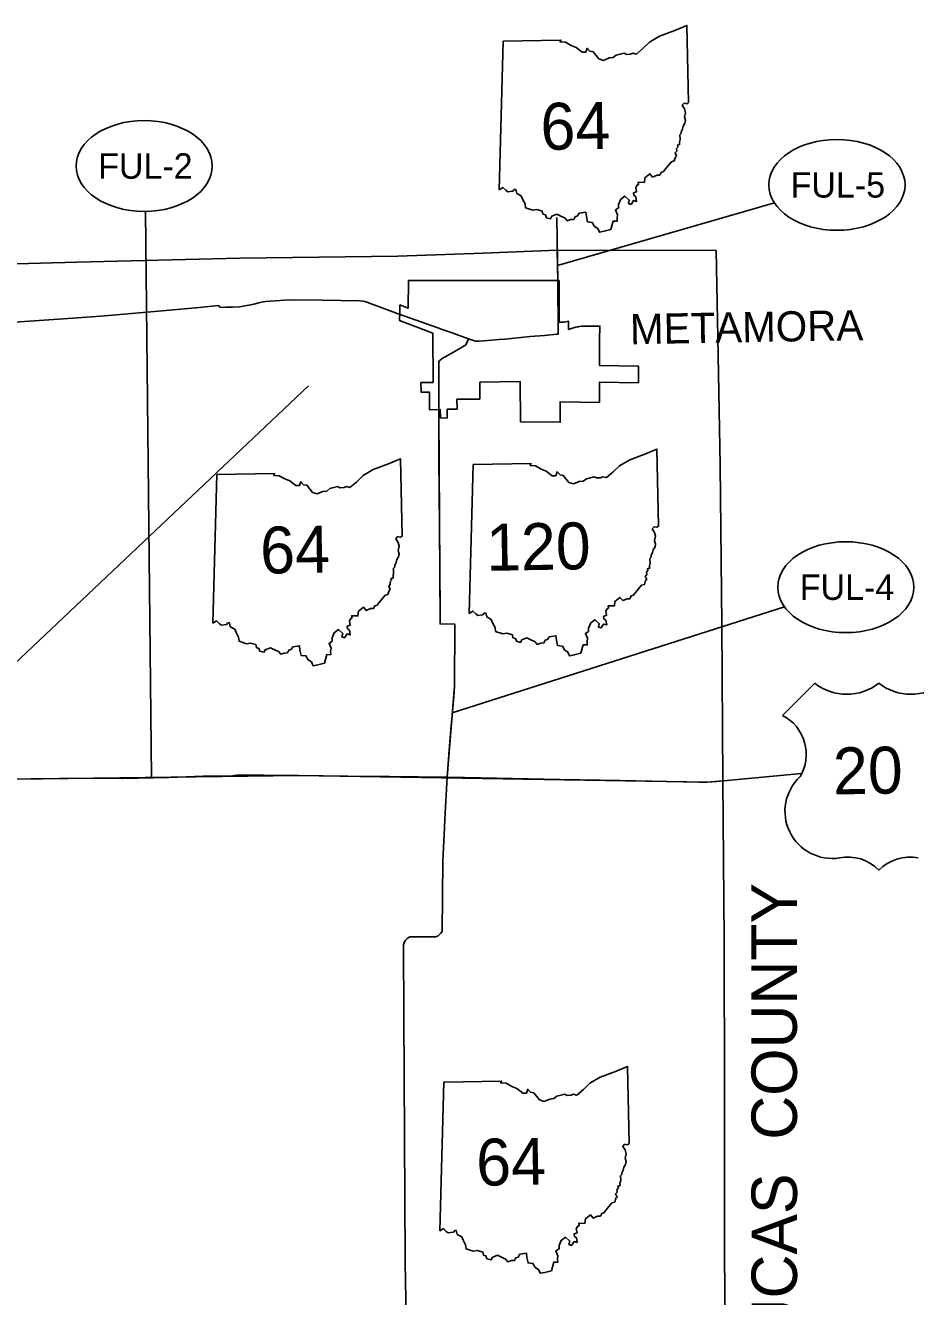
# Model space of a CAD drawing. Extents: x 0 to 849, y 0 to 440.
# Drawn here: x 488.2 to 586.2, y 214.9 to 354.8 of the extents above; entities that cross this region are included whole.
import ezdxf

# ---------------------------------------------------------------- set-up
doc = ezdxf.new("R2010")
doc.units = 0
for name, color, linetype in [('DV_X_Corp_Line', 7, 'Continuous'), ('GM_X_Adjacent_County_Text', 7, 'Continuous'), ('GM_X_Corporation_Text', 7, 'Continuous'), ('GM_X_County', 7, 'Continuous'), ('GM_X_Interstate_Route', 7, 'Continuous'), ('PV_P_Walk', 7, 'Continuous'), ('RD_P_Fence', 7, 'Continuous'), ('RD_X_RR_2', 7, 'Continuous'), ('SH_Data', 7, 'Continuous')]:
    doc.layers.add(name, color=color, linetype=linetype)

msp = doc.modelspace()

# ---------------------------------------------------------------- linework, layer by layer
at = {"layer": 'DV_X_Corp_Line'}
msp.add_lwpolyline([(529.44, 324.07), (530.37, 323.7), (530.41, 326.76), (546.98, 326.74), (546.99, 322.8), (547, 322.15), (547.26, 322.14), (547.56, 322.16), (548.02, 322.27), (548.03, 321.36), (548.46, 321.51), (548.84, 321.61), (548.96, 321.64), (549.1, 321.66), (549.44, 321.71), (549.74, 321.72), (549.95, 321.72), (551.48, 321.73), (551.47, 320.98), (551.43, 320.98), (551.42, 317.39), (555.73, 317.33), (555.73, 315.49), (551.43, 315.55), (551.43, 313.32), (547.09, 313.38), (547.11, 311.14), (542.74, 311.2), (542.69, 315.64), (538.27, 315.54), (538.25, 313.68), (535.73, 313.67), (535.75, 312.58), (534.65, 312.57), (534.66, 311.6), (533.91, 311.64), (533.9, 312.54), (532.7, 312.52), (532.72, 313.78), (532.7, 314.45), (531.81, 314.44), (531.77, 315.51), (533.12, 315.52), (533.08, 320.96), (529.41, 322.34), (529.44, 323.25)], close=True, dxfattribs=at)
at = {"layer": 'GM_X_County'}
msp.add_lwpolyline([(390.27, 326.72), (403.53, 326.93), (421.18, 327.57), (438.99, 327.93), (455.38, 327.76), (456.49, 327.78), (456.55, 327.79), (476.51, 328.3), (493.89, 328.75), (511.84, 329.22), (529.24, 329.42), (538.61, 329.77), (546.79, 330.09), (564.28, 330.05), (564.46, 320.49), (564.74, 306.39), (564.89, 288.89), (565.03, 271.67), (565.17, 254.2), (565.19, 237.05), (565.2, 232.33), (565.21, 219.21), (565.34, 205.31)], dxfattribs=at)
at = {"layer": 'GM_X_Interstate_Route'}
msp.add_line((533.88, 290.45), (533.78, 303.7), dxfattribs=at)
for points in [[(546.83, 326.65), (546.75, 333.68)], [(546.88, 321.94), (546.87, 323.41), (546.86, 324.47), (546.83, 326.65)], [(458.99, 319.55), (482.08, 321.71), (487.07, 322.14), (491.86, 322.48), (493.95, 322.64), (496.53, 322.83), (502.87, 323.38), (507.37, 323.78), (509.49, 323.99), (509.55, 323.89), (509.68, 323.81), (510, 323.78), (510.29, 323.79)], [(510.29, 323.79), (510.3, 323.79), (511.04, 323.79), (511.78, 323.86), (513.24, 324.11), (513.93, 324.28), (513.93, 324.28)], [(513.93, 324.28), (514.23, 324.36), (514.64, 324.42), (516.74, 324.59), (517.3, 324.62), (520.91, 324.57), (525, 324.51), (525.41, 324.46), (525.6, 324.44), (525.83, 324.36), (529.28, 323.09)], [(529.28, 323.09), (533.75, 321.49), (533.89, 321.44), (533.9, 321.44)], [(546.72, 320.83), (546.72, 320.83), (546.89, 320.85), (546.88, 321.93), (546.88, 321.94)], [(533.9, 321.44), (534.98, 321.06), (535.32, 320.93), (535.38, 320.91)], [(535.38, 320.91), (537.02, 320.31)], [(539.55, 320.18), (539.55, 320.18), (540.4, 320.25), (541.06, 320.3), (543.82, 320.56)], [(543.82, 320.56), (543.82, 320.56), (545.39, 320.7), (546.72, 320.83)], [(535.35, 318.86), (536.6, 319.58), (536.71, 319.65), (536.72, 319.68), (536.79, 319.81), (537.02, 320.31)], [(537.02, 320.31), (537.44, 320.16), (537.79, 320.07), (537.84, 320.07)], [(537.84, 320.07), (538, 320.07), (538.15, 320.07), (538.66, 320.11), (539.55, 320.18)], [(533.75, 313.56), (533.74, 315), (533.74, 315.51), (533.74, 317.16), (533.73, 317.82), (533.83, 317.92), (533.84, 317.93), (533.85, 317.94)], [(533.85, 317.94), (534.11, 318.15), (535.35, 318.86)], [(533.76, 311.8), (533.76, 312.02), (533.76, 312.14), (533.75, 313.56)], [(533.76, 311.44), (533.76, 311.8)], [(533.78, 303.7), (533.76, 306.84), (533.76, 311.44)], [(535.12, 277.75), (535.14, 278.06), (535.41, 280.93), (535.43, 281.51), (535.47, 282.09), (535.49, 288.91), (533.89, 288.94), (533.88, 290.45)], [(534.65, 272.06), (534.81, 274.04), (534.86, 274.55), (535.12, 277.75)], [(473.29, 271.88), (477.19, 271.85), (485.05, 271.86), (488.86, 271.88), (490.09, 271.89), (493.69, 271.94), (498.86, 271.92), (498.96, 271.92), (504.03, 272.04), (507.8, 272.16), (507.87, 272.16), (510.81, 272.18), (511.47, 272.28), (512.4, 272.32), (516.54, 272.25), (518.32, 272.23), (523.68, 272.16), (527.6, 272.15), (528.32, 272.14)], [(528.32, 272.14), (534.65, 272.06)], [(534.41, 267.43), (534.65, 272.06)], [(534.65, 272.06), (536.57, 272.02), (543.6, 271.87), (547.07, 271.81)], [(547.07, 271.81), (547.07, 271.81), (553.66, 271.69), (562.36, 271.5), (563.3, 271.51), (564.33, 271.6), (573.67, 272.48)], [(529.86, 253.44), (529.86, 253.44), (529.86, 253.62), (529.92, 253.85), (530.09, 254.13), (530.26, 254.31), (530.55, 254.48), (533.4, 254.49), (533.68, 254.61), (533.94, 254.84), (534.11, 255.08), (534.19, 262.81), (534.36, 266.52), (534.41, 267.43)], [(530.04, 218.98), (529.9, 245.88), (529.86, 253.44)], [(530.16, 212.32), (530.11, 214.87), (530.08, 216.27), (530.04, 218.98)]]:
    msp.add_lwpolyline(points, dxfattribs=at)
at = {"layer": 'PV_P_Walk'}
for p, q in [((540.38, 336.73), (540.84, 353.1)), ((540.38, 336.73), (540.84, 353.1)), ((508.85, 289.01), (509.3, 305.38)), ((537.08, 290.1), (537.54, 306.47)), ((575.14, 282.41), (571.59, 278.86)), ((533.84, 222.12), (534.3, 238.49))]:
    msp.add_line(p, q, dxfattribs=at)
for points in [[(540.84, 353.1), (547.19, 353.21), (547.09, 353.01), (547.69, 352.97), (548.33, 352.62), (548.87, 352.4), (549.53, 351.88), (549.92, 351.89), (550.09, 352.31), (550.39, 351.98), (550.75, 351.92), (551.37, 351.14), (551.88, 350.97), (552.49, 351.24), (552.95, 351.28), (553.28, 351.55), (554.16, 351.78), (554.4, 351.64), (554.86, 351.67), (555.09, 351.77), (555.5, 351.68), (556.2, 352.27), (556.93, 352.98), (558.06, 353.64), (559.73, 354.26), (561.06, 354.83), (561.25, 346.33)], [(540.84, 353.1), (547.19, 353.21), (547.09, 353.01), (547.69, 352.97), (548.33, 352.62), (548.87, 352.4), (549.53, 351.88), (549.92, 351.89), (550.09, 352.31), (550.39, 351.98), (550.75, 351.92), (551.37, 351.14), (551.88, 350.97), (552.49, 351.24), (552.95, 351.28), (553.28, 351.55), (554.16, 351.78), (554.4, 351.64), (554.86, 351.67), (555.09, 351.77), (555.5, 351.68), (556.2, 352.27), (556.93, 352.98), (558.06, 353.64), (559.73, 354.26), (561.06, 354.83), (561.25, 346.33)], [(561.25, 346.33), (561.05, 346.21), (560.75, 346.27), (560.54, 346.03), (560.8, 345.63), (560.92, 345.21), (560.81, 344.75), (560.91, 344.37), (560.84, 344.05), (560.65, 343.73), (560.59, 343.42), (560.42, 343.1), (560.44, 342.93), (560.28, 342.78), (560.31, 342.25), (560.23, 341.96), (560.26, 341.7), (560.01, 341.64), (560.06, 341.43), (559.9, 341.27), (559.94, 340.99), (559.76, 340.81), (559.93, 340.45), (559.79, 340.34), (559.67, 339.91), (559.35, 339.82), (558.71, 339.02), (558.48, 338.73), (558.22, 338.65), (558.08, 338.34), (557.77, 338.34), (557.29, 338.13), (556.98, 338.5), (556.44, 338.05), (556.38, 337.54), (555.69, 337.56), (555.72, 337.3), (555.57, 337.23), (555.43, 336.97), (555.51, 336.51), (555.19, 336.39), (555.23, 336.12), (555.43, 335.96), (555.52, 335.45), (555.18, 335.55), (554.91, 335.12), (554.62, 335.23), (554.71, 335.59), (554.23, 336.03), (553.77, 335.68), (553.53, 335.12), (553.53, 334.74), (553.19, 334.51), (553.41, 333.98), (553.37, 333.61), (553.37, 333.26), (552.95, 333.28), (552.69, 332.34)], [(561.25, 346.33), (561.05, 346.21), (560.75, 346.27), (560.54, 346.03), (560.8, 345.63), (560.92, 345.21), (560.81, 344.75), (560.91, 344.37), (560.84, 344.05), (560.65, 343.73), (560.59, 343.42), (560.42, 343.1), (560.44, 342.93), (560.28, 342.78), (560.31, 342.25), (560.23, 341.96), (560.26, 341.7), (560.01, 341.64), (560.06, 341.43), (559.9, 341.27), (559.94, 340.99), (559.76, 340.81), (559.93, 340.45), (559.79, 340.34), (559.67, 339.91), (559.35, 339.82), (558.71, 339.02), (558.48, 338.73), (558.22, 338.65), (558.08, 338.34), (557.77, 338.34), (557.29, 338.13), (556.98, 338.5), (556.44, 338.05), (556.38, 337.54), (555.69, 337.56), (555.72, 337.3), (555.57, 337.23), (555.43, 336.97), (555.51, 336.51), (555.19, 336.39), (555.23, 336.12), (555.43, 335.96), (555.52, 335.45), (555.18, 335.55), (554.91, 335.12), (554.62, 335.23), (554.71, 335.59), (554.23, 336.03), (553.77, 335.68), (553.53, 335.12), (553.53, 334.74), (553.19, 334.51), (553.41, 333.98), (553.37, 333.61), (553.37, 333.26), (552.95, 333.28), (552.69, 332.34)], [(552.69, 332.34), (551.95, 332.16), (551.43, 332.05), (551.25, 332.48), (550.88, 332.7), (550.64, 333.13), (550.12, 333.19), (549.99, 333.78), (549.93, 334.26), (549.21, 334.14), (549.01, 333.85), (548.75, 333.77), (548.61, 333.47), (548.26, 333.45), (547.88, 333.31), (547.64, 333.6), (547.02, 333.89), (546.75, 334.04), (546.17, 333.81), (546.04, 333.53), (545.59, 333.65), (545.48, 333.96), (545.2, 334.05), (545.14, 334.38), (544.54, 334.55), (544.09, 334.48), (543.29, 334.75), (543.24, 335.18), (542.97, 335.7), (542.82, 336.06), (542.32, 336.34), (542.21, 336.77), (542.05, 336.76), (541.9, 336.58), (541.34, 336.5), (541.11, 336.68), (540.8, 336.98), (540.38, 336.73)], [(552.69, 332.34), (551.95, 332.16), (551.43, 332.05), (551.25, 332.48), (550.88, 332.7), (550.64, 333.13), (550.12, 333.19), (549.99, 333.78), (549.93, 334.26), (549.21, 334.14), (549.01, 333.85), (548.75, 333.77), (548.61, 333.47), (548.26, 333.45), (547.88, 333.31), (547.64, 333.6), (547.02, 333.89), (546.75, 334.04), (546.17, 333.81), (546.04, 333.53), (545.59, 333.65), (545.48, 333.96), (545.2, 334.05), (545.14, 334.38), (544.54, 334.55), (544.09, 334.48), (543.29, 334.75), (543.24, 335.18), (542.97, 335.7), (542.82, 336.06), (542.32, 336.34), (542.21, 336.77), (542.05, 336.76), (541.9, 336.58), (541.34, 336.5), (541.11, 336.68), (540.8, 336.98), (540.38, 336.73)], [(537.54, 306.47), (543.9, 306.58), (543.8, 306.38), (544.4, 306.34), (545.03, 305.99), (545.57, 305.77), (546.23, 305.25), (546.62, 305.25), (546.79, 305.68), (547.09, 305.35), (547.45, 305.29), (548.07, 304.51), (548.58, 304.34), (549.19, 304.61), (549.65, 304.65), (549.99, 304.92), (550.86, 305.14), (551.1, 305.01), (551.56, 305.03), (551.79, 305.14), (552.2, 305.05), (552.91, 305.64), (553.64, 306.34), (554.76, 307.01), (556.43, 307.63), (557.76, 308.19), (557.95, 299.7)], [(509.3, 305.38), (515.66, 305.49), (515.56, 305.29), (516.16, 305.25), (516.79, 304.9), (517.33, 304.68), (517.99, 304.16), (518.39, 304.17), (518.55, 304.59), (518.85, 304.26), (519.21, 304.2), (519.83, 303.42), (520.34, 303.25), (520.96, 303.52), (521.41, 303.56), (521.75, 303.83), (522.62, 304.06), (522.86, 303.92), (523.32, 303.95), (523.56, 304.05), (523.96, 303.96), (524.67, 304.55), (525.4, 305.26), (526.52, 305.92), (528.19, 306.55), (529.52, 307.11), (529.71, 298.61)], [(557.95, 299.7), (557.75, 299.58), (557.45, 299.63), (557.24, 299.4), (557.5, 299), (557.62, 298.58), (557.51, 298.11), (557.62, 297.73), (557.55, 297.41), (557.35, 297.1), (557.29, 296.79), (557.13, 296.47), (557.14, 296.29), (556.98, 296.15), (557.01, 295.62), (556.93, 295.33), (556.96, 295.07), (556.71, 295.01), (556.77, 294.8), (556.61, 294.63), (556.64, 294.35), (556.46, 294.18), (556.64, 293.82), (556.49, 293.71), (556.38, 293.27), (556.05, 293.19), (555.41, 292.39), (555.18, 292.09), (554.92, 292.02), (554.78, 291.71), (554.47, 291.71), (553.99, 291.5), (553.68, 291.86), (553.14, 291.42), (553.08, 290.91), (552.4, 290.93), (552.42, 290.67), (552.27, 290.59), (552.13, 290.33), (552.21, 289.88), (551.89, 289.76), (551.93, 289.49), (552.13, 289.33), (552.23, 288.82), (551.89, 288.92), (551.61, 288.49), (551.32, 288.59), (551.41, 288.96), (550.93, 289.39), (550.47, 289.04), (550.23, 288.48), (550.23, 288.11), (549.89, 287.88), (550.11, 287.35), (550.07, 286.98), (550.08, 286.63), (549.65, 286.64), (549.39, 285.7)], [(529.71, 298.61), (529.52, 298.49), (529.21, 298.55), (529.01, 298.31), (529.26, 297.91), (529.38, 297.49), (529.27, 297.03), (529.38, 296.65), (529.31, 296.33), (529.12, 296.01), (529.05, 295.71), (528.89, 295.39), (528.9, 295.21), (528.75, 295.07), (528.77, 294.53), (528.7, 294.24), (528.72, 293.99), (528.47, 293.92), (528.53, 293.71), (528.37, 293.55), (528.4, 293.27), (528.22, 293.09), (528.4, 292.73), (528.26, 292.62), (528.14, 292.19), (527.82, 292.1), (527.17, 291.31), (526.94, 291.01), (526.69, 290.93), (526.54, 290.62), (526.23, 290.62), (525.75, 290.41), (525.44, 290.78), (524.9, 290.33), (524.84, 289.82), (524.16, 289.84), (524.18, 289.58), (524.03, 289.51), (523.89, 289.25), (523.97, 288.79), (523.65, 288.67), (523.69, 288.4), (523.9, 288.24), (523.99, 287.73), (523.65, 287.84), (523.37, 287.41), (523.08, 287.51), (523.18, 287.87), (522.69, 288.31), (522.23, 287.96), (522, 287.4), (521.99, 287.02), (521.65, 286.79), (521.87, 286.26), (521.83, 285.89), (521.84, 285.54), (521.41, 285.56), (521.15, 284.62)], [(549.39, 285.7), (548.65, 285.52), (548.13, 285.42), (547.95, 285.84), (547.59, 286.07), (547.35, 286.5), (546.82, 286.56), (546.69, 287.15), (546.63, 287.63), (545.91, 287.51), (545.71, 287.22), (545.46, 287.14), (545.31, 286.84), (544.96, 286.82), (544.58, 286.68), (544.34, 286.97), (543.72, 287.26), (543.45, 287.41), (542.87, 287.17), (542.75, 286.9), (542.29, 287.02), (542.18, 287.33), (541.9, 287.42), (541.84, 287.75), (541.25, 287.92), (540.79, 287.85), (539.99, 288.11), (539.94, 288.54), (539.67, 289.07), (539.52, 289.43), (539.02, 289.71), (538.91, 290.14), (538.75, 290.12), (538.6, 289.95), (538.04, 289.87), (537.82, 290.05), (537.5, 290.35), (537.08, 290.1)], [(521.15, 284.62), (520.41, 284.44), (519.9, 284.33), (519.72, 284.76), (519.35, 284.98), (519.11, 285.41), (518.58, 285.47), (518.45, 286.06), (518.39, 286.54), (517.67, 286.42), (517.47, 286.13), (517.22, 286.05), (517.07, 285.75), (516.72, 285.73), (516.35, 285.59), (516.1, 285.88), (515.49, 286.17), (515.21, 286.32), (514.63, 286.09), (514.51, 285.81), (514.05, 285.93), (513.94, 286.24), (513.66, 286.33), (513.6, 286.66), (513.01, 286.83), (512.55, 286.76), (511.75, 287.03), (511.7, 287.46), (511.43, 287.98), (511.29, 288.34), (510.78, 288.62), (510.68, 289.05), (510.51, 289.04), (510.37, 288.86), (509.8, 288.78), (509.58, 288.96), (509.26, 289.26), (508.85, 289.01)], [(534.3, 238.49), (540.65, 238.6), (540.55, 238.4), (541.15, 238.36), (541.79, 238.01), (542.32, 237.79), (542.98, 237.27), (543.38, 237.27), (543.54, 237.7), (543.85, 237.37), (544.2, 237.31), (544.82, 236.53), (545.33, 236.36), (545.95, 236.63), (546.4, 236.67), (546.74, 236.94), (547.61, 237.16), (547.85, 237.03), (548.32, 237.05), (548.55, 237.15), (548.95, 237.06), (549.66, 237.66), (550.39, 238.36), (551.51, 239.02), (553.19, 239.65), (554.51, 240.21), (554.7, 231.72)], [(554.7, 231.72), (554.51, 231.6), (554.2, 231.65), (554, 231.41), (554.25, 231.02), (554.37, 230.6), (554.27, 230.13), (554.37, 229.75), (554.3, 229.43), (554.11, 229.11), (554.04, 228.81), (553.88, 228.49), (553.89, 228.31), (553.74, 228.17), (553.77, 227.64), (553.69, 227.35), (553.71, 227.09), (553.46, 227.02), (553.52, 226.81), (553.36, 226.65), (553.39, 226.37), (553.21, 226.2), (553.39, 225.84), (553.25, 225.73), (553.13, 225.29), (552.81, 225.2), (552.16, 224.41), (551.93, 224.11), (551.68, 224.04), (551.54, 223.73), (551.22, 223.73), (550.74, 223.52), (550.44, 223.88), (549.89, 223.44), (549.83, 222.93), (549.15, 222.95), (549.18, 222.69), (549.02, 222.61), (548.88, 222.35), (548.96, 221.89), (548.64, 221.78), (548.68, 221.51), (548.89, 221.35), (548.98, 220.84), (548.64, 220.94), (548.36, 220.51), (548.07, 220.61), (548.17, 220.98), (547.68, 221.41), (547.23, 221.06), (546.99, 220.5), (546.98, 220.13), (546.64, 219.9), (546.86, 219.37), (546.82, 219), (546.83, 218.65), (546.4, 218.66), (546.14, 217.72)], [(546.14, 217.72), (545.4, 217.54), (544.89, 217.44), (544.71, 217.86), (544.34, 218.09), (544.1, 218.52), (543.57, 218.58), (543.45, 219.17), (543.39, 219.65), (542.66, 219.53), (542.47, 219.23), (542.21, 219.16), (542.06, 218.86), (541.71, 218.84), (541.34, 218.7), (541.09, 218.99), (540.48, 219.28), (540.2, 219.43), (539.62, 219.19), (539.5, 218.92), (539.04, 219.04), (538.93, 219.35), (538.66, 219.44), (538.59, 219.77), (538, 219.94), (537.54, 219.87), (536.74, 220.13), (536.69, 220.56), (536.42, 221.08), (536.28, 221.45), (535.77, 221.73), (535.67, 222.16), (535.51, 222.14), (535.36, 221.97), (534.79, 221.89), (534.57, 222.06), (534.25, 222.37), (533.84, 222.12)]]:
    msp.add_lwpolyline(points, dxfattribs=at)
for centre, radius, start, end in [((578.66, 286.89), 5.7, 231.813, 308.187), ((585.71, 286.89), 5.7, 231.813, 308.187), ((569.38, 274.58), 4.82, 329.1175, 62.6108), ((577.06, 268.31), 5.2, 133.0046, 278.7282), ((578.81, 258.62), 4.65, 43.4177, 101.8742), ((585.66, 258.31), 4.94, 79.9613, 134.7468), ((585.66, 258.31), 4.94, 79.9613, 134.7468)]:
    msp.add_arc(centre, radius, start, end, dxfattribs=at)
at = {"layer": 'RD_P_Fence'}
msp.add_line((546.79, 330.05), (546.79, 330.05), dxfattribs=at)
at = {"layer": 'RD_X_RR_2'}
msp.add_lwpolyline([(456.64, 255.85), (519.4, 315.15)], dxfattribs=at)
at = {"layer": 'SH_Data'}
for p, q in [((570.7, 335.28), (546.81, 328.41)), ((501.43, 334.35), (502.12, 272.04)), ((546.83, 326.65), (546.79, 330.09)), ((571.8, 290.82), (535.23, 279.15))]:
    msp.add_line(p, q, dxfattribs=at)
for points in [[(533.76, 312.14), (533.89, 288.94), (535.49, 288.91), (535.47, 282.09), (534.65, 272.06)], [(490.09, 271.89), (518.32, 272.23), (563.3, 271.51), (565.03, 271.67)]]:
    msp.add_lwpolyline(points, dxfattribs=at)
for centre in [(501.3, 339.35), (577.58, 337.27), (578.56, 292.98)]:
    msp.add_ellipse(centre, major_axis=(7.5, 0), ratio=0.666667, dxfattribs=at)

# ---------------------------------------------------------------- texts
at = {"layer": 'GM_X_Adjacent_County_Text'}
msp.add_text('LUCAS  COUNTY', height=5.0058, rotation=90.0231, dxfattribs=at).set_placement((573.19, 206.11))
at = {"layer": 'GM_X_Corporation_Text'}
msp.add_text('METAMORA', height=3.325, rotation=1.0142, dxfattribs=at).set_placement((554.82, 319.72))
at = {"layer": 'PV_P_Walk'}
for s, p in [('64', (544.98, 341.11)), ('64', (514.11, 294.46)), ('120', (538.99, 294.77)), ('20', (577.19, 270.15)), ('64', (537.9, 227.07))]:
    msp.add_text(s, height=5.162, rotation=1.0142, dxfattribs=at).set_placement(p)
at = {"layer": 'SH_Data'}
for s, p in [('FUL-2', (496.23, 337.95)), ('FUL-5', (572.48, 335.87)), ('FUL-4', (573.49, 291.58))]:
    msp.add_text(s, height=2.8, dxfattribs=at).set_placement(p)

doc.saveas('drawing.dxf')
